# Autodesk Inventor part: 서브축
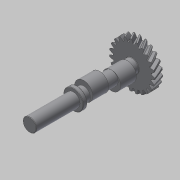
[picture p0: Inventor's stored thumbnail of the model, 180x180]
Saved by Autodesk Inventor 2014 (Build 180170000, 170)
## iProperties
Created: 2016-12
Part Number: 서브축
Material: 강철, 탄소
Document SubType Name: Modeling
Designer: mduedu
Categories: <?xml version="1.0" encoding="UTF-16"?> <MemberInstance><Categories><FamilyTemplate><FamilyTemplateParameter ValueType="xs:double" Id="1" ObjectReferenceKey="da
Density: 7.87 g/cm^3
Mass: 484.101 g
Surface Area: 171.575 cm^2
Volume: 61.5122 cm^3
Appearance: 기본값
CustomPartVersion: 1
Author: mduedu
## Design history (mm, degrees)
sketch "Sketch1"
  geometry: C1 r 28.558 at (0, 0)
  constraints: 1 centre point
  dimensions: "d0" = 57.11622 diameter of C1 (= da_da)
extrude "Extrusion1" new body sketch "Sketch1" distance "d1" = 10 (= da_b); taper "d2" = 0 deg
workplane "Work Plane2"
sketch "Sketch2"
  geometry: C1 r 28.558 at (0, 0) reference; C2 r 26.558 at (0, 0)
  constraints: 1 centre point, 1 coincident
  dimensions: "d3" = 53.11622 diameter of C2 (= da_dw)
feature "피치 지름" sketch "Sketch2" dims "d4" = 10, "d5" = 0
workplane "Work Plane8"
workplane "Work Plane9"
feature "스퍼 기어" dims "da_b" = 10, "da_d" = 53.11622, "da_aw" = 43.87862, "da_da" = 57.11622, "da_df" = 48.11622, "da_dw" = 53.11622, angle "da_beta" = 30 deg, "da_lefttooth" = 10, "da_righttooth" = 0
sketch "스케치3"
  geometry: C1 r 12.5 at (0, 0); 1 further point
  constraints: 1 centre point, 1 coincident
  dimensions: "d49" = 25 diameter of C1
extrude "돌출2" join sketch "스케치3" distance "d50" = 6; taper "d51" = 0 deg
sketch "스케치4"
  geometry: C1 r 8.5 at (0, 0); 1 further point
  constraints: 1 centre point, 1 coincident
  dimensions: "d52" = 17 diameter of C1
extrude "돌출3" join sketch "스케치4" distance "d53" = 123; taper "d54" = 0 deg
sketch "스케치5"
  geometry: C1 r 7.5 at (0, 0); 1 further point
  constraints: 1 centre point, 1 coincident
  dimensions: "d55" = 15 diameter of C1
extrude "돌출4" join sketch "스케치5" distance "d56" = 6; taper "d57" = 0 deg
sketch "스케치6"
  geometry: C1 r 4 at (0, 0); 1 further point
  constraints: 1 centre point, 1 coincident
  dimensions: "d58" = 8 diameter of C1
extrude "돌출5" join sketch "스케치6" distance "d59" = 7; taper "d60" = 0 deg
chamfer "모따기1" distance "d61" = 0.5; stored, may be unused: second distance "d62" = 2, angle "d63" = 45 deg
fillet "모깎기1" dims "d64" = 0.5
node "작업 평면11"
sketch "스케치7"
  geometry: C1 r 11.5 at (0, 3); C2 r 8.5 at (0, 0) reference; 1 further point
  constraints: 1 centre point, 1 tangent, 1 vertical alignment
  dimensions: "d66" = 3 distance of point (0, 0) C1.centre; "d67" = 23 diameter of C1 (derived)
extrude "돌출6" join sketch "스케치7" stored distance "d68" = 20; taper "d69" = 0 deg
node "작업 평면13"
sketch "스케치9"
  geometry: C1 r 11.5 at (0, -3); C2 r 8.5 at (0, 0) reference; 1 further point
  constraints: 1 centre point, 1 tangent, 1 vertical alignment
  dimensions: "d78" = 3 distance of C1.centre point (0, 0); "d79" = 23 diameter of C1 (derived)
extrude "돌출8" join sketch "스케치9" stored distance "d80" = 20; taper "d81" = 0 deg
node "작업 평면12"
sketch "스케치8"
  geometry: C1 r 12.5 at (0, 0) reference; 1 further point
extrude "돌출7" join sketch "스케치8" distance "d71" = 5; taper "d72" = 0 deg
chamfer "모따기2" distance "d73" = 0.5; stored, may be unused: second distance "d74" = 2, angle "d75" = 45 deg
sketch "스케치10"
  geometry: C1 r 12.5 at (0, 0) reference; C2 r 8.5 at (0, 0) reference; 1 further point
extrude "돌출9" cut sketch "스케치10" stored distance "d82" = 20; taper "d83" = 0 deg
fillet "모깎기2" dims "d84" = 0.5
body "Solid1"
body "Srf1"
other parameters: "d16" = 43.87862 (= da_aw), "d17" = 0, "d34" = 1.36591 (computed from da_z), "d39" = 0, "d41" = 0, "d43" = 43.87862 (= da_aw), "d46" = 43.87862 (= da_aw), "d47" = 0, "d48" = 0, "d65" = 45, "d70" = 68, "d76" = -35
